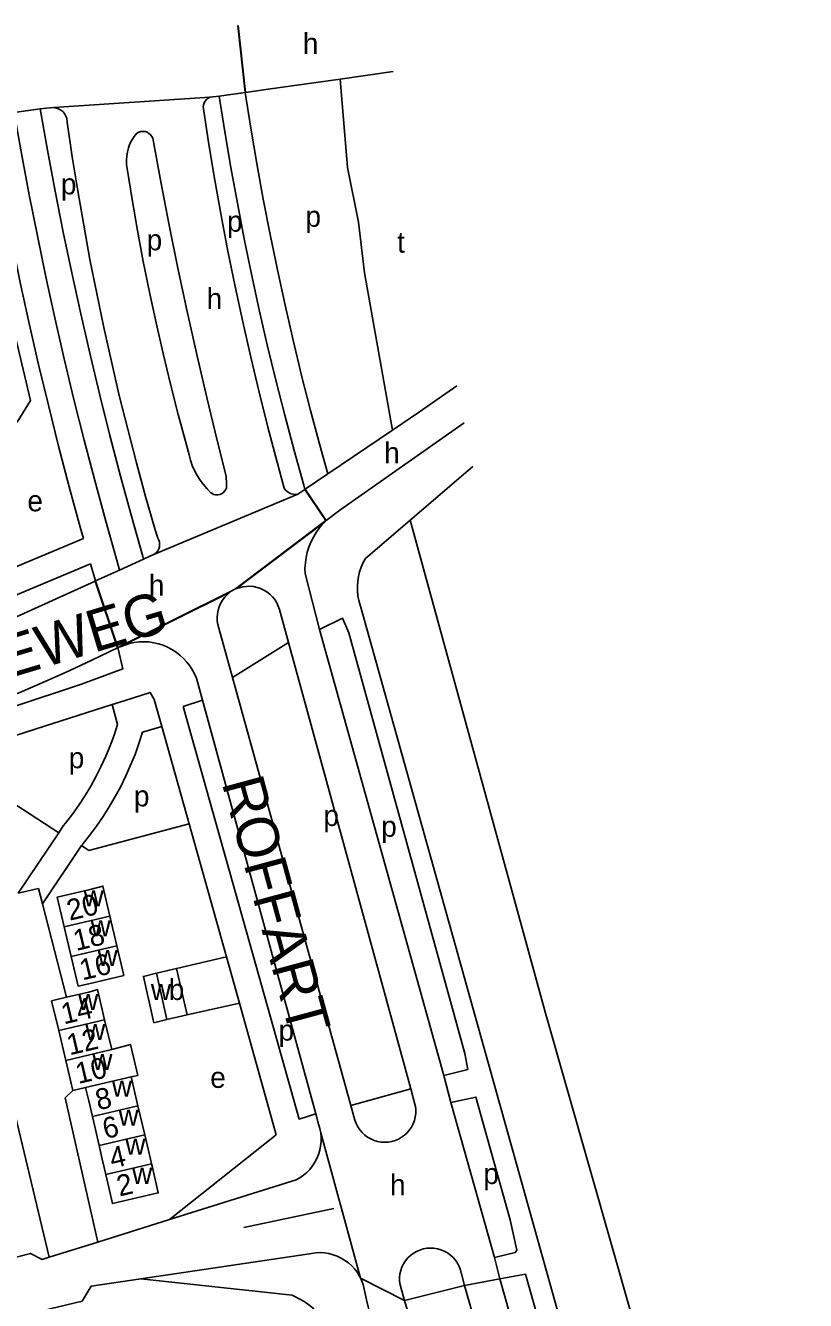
# Model space of a CAD drawing. Extents: x 157646 to 159241, y 379213 to 381217.
# Drawn here: x 158987.9 to 159137, y 380973 to 381216.8 of the extents above; entities that cross this region are included whole.
import ezdxf

# ---------------------------------------------------------------- set-up
doc = ezdxf.new("R2010")
doc.units = 0
for name, color, linetype in [('BLT_Basislijn', 7, 'Continuous'), ('BLT_Bebouwing', 7, 'Continuous'), ('BLT_Centroide', 7, 'Continuous'), ('BLT_Huisnummer', 7, 'Continuous'), ('BLT_Huisnummer_ tussenligend', 7, 'Continuous'), ('BLT_Onderverdeling_panden', 7, 'Continuous'), ('BLT_Straatnaam_hoofdweg', 7, 'Continuous'), ('BLT_Vlakafsluiter', 7, 'Continuous')]:
    doc.layers.add(name, color=color, linetype=linetype)

msp = doc.modelspace()

# ---------------------------------------------------------------- linework, layer by layer
at = {"layer": 'BLT_Basislijn'}
for p, q in [((159058.2, 381207.99), (159048.02, 381206.55)), ((159034.27, 381204.61), (159048.02, 381206.55)), ((159023.15, 381203.13), (159024.93, 381203.32)), ((159024.93, 381203.32), (159029.88, 381204)), ((159029.88, 381204), (159029.93, 381204.01)), ((159029.93, 381204.01), (159034.27, 381204.61)), ((158985.74, 381200.19), (158990.7, 381200.86)), ((158990.7, 381200.86), (158991.92, 381201.02)), ((158991.92, 381201.02), (158993.29, 381201.11)), ((158995.77, 381199.08), (158995.87, 381198.3)), ((159045.68, 381131.05), (159058.05, 381139.43)), ((159073.44, 381132.44), (159061.42, 381122.18)), ((159026.24, 381130.64), (159026.31, 381129.18)), ((159041.36, 381128.13), (159045.68, 381131.05)), ((159039.96, 381127.17), (159041.32, 381128.1)), ((159041.32, 381128.1), (159041.36, 381128.13)), ((159047.97, 381124.14), (159045.36, 381122.16)), ((159045.1, 381121.9), (159045.32, 381122.13)), ((159045.36, 381122.16), (159045.32, 381122.13)), ((159061.42, 381122.18), (159052.88, 381114.89)), ((158998.95, 381118.71), (158958.63, 381101.7)), ((159010.47, 381114.75), (159011.68, 381115.3)), ((159012.58, 381115.68), (159011.68, 381115.3)), ((159000.32, 381113.86), (158956.44, 381095.51)), ((159000.32, 381113.86), (159001.27, 381110.58)), ((159001.27, 381110.58), (159005.87, 381112.66)), ((159005.87, 381112.66), (159010.47, 381114.75)), ((159041.33, 381112), (159044.1, 381101.28)), ((159026.86, 381108.37), (159026.96, 381108.48)), ((159026.96, 381108.48), (159028.07, 381109.07)), ((159028.07, 381109.07), (159028.22, 381109.11)), ((159038.16, 381098.82), (159036.43, 381105.12)), ((159024.84, 381101.57), (159027.45, 381092.14)), ((159044.1, 381101.28), (159067.87, 381016.03)), ((159005.55, 381097.83), (159005.98, 381097.99)), ((159038.16, 381098.82), (159027.45, 381092.14)), ((159061.54, 381013.44), (159038.16, 381098.82)), ((159005.5, 381097.81), (159005.55, 381097.83)), ((159020.57, 381091.97), (159021.7, 381087.81)), ((159027.45, 381092.14), (159050.11, 381010.24)), ((159005.5, 381083.11), (159004.49, 381086.94)), ((159012.49, 381087.89), (159013.94, 381082.74)), ((159018.05, 381086.59), (159021.7, 381087.81)), ((159018.05, 381086.59), (159040.2, 381007.62)), ((159021.7, 381087.81), (159043.38, 381008.65)), ((159010.28, 381081.64), (159013.94, 381082.74)), ((159013.94, 381082.74), (159019.15, 381064.15)), ((159000, 381059.01), (159019.15, 381064.15)), ((159019.15, 381064.15), (159026.3, 381038.67)), ((158994.25, 381062.43), (158986.48, 381050.9)), ((158995.12, 381063.72), (158994.25, 381062.43)), ((158998.63, 381060.01), (158991.13, 381048.86)), ((159000, 381059.01), (158998.63, 381060.01)), ((158986.48, 381050.9), (158990.38, 381051.79)), ((158990.38, 381051.79), (158991.13, 381048.86)), ((158991.13, 381048.86), (158995.73, 381030.98)), ((159016.73, 381036.46), (159026.3, 381038.67)), ((159026.3, 381038.67), (159028.78, 381029.82)), ((159018.8, 381027.59), (159028.78, 381029.82)), ((159028.78, 381029.82), (159035.84, 381004.65)), ((159067.87, 381016.03), (159069.18, 381010.85)), ((159061.54, 381013.44), (159050.11, 381010.24)), ((159062.4, 381010.28), (159061.54, 381013.44)), ((159050.11, 381010.24), (159050.88, 381007.46)), ((159077.52, 380981.2), (159069.18, 381010.85)), ((158992.44, 380981.26), (158985.59, 381009.81)), ((159040.2, 381007.62), (159043.38, 381008.65)), ((159043.38, 381008.65), (159043.91, 381006.69)), ((159035.84, 381004.65), (159015.44, 380988.46)), ((159015.44, 380988.46), (159039.61, 380996.03)), ((159001.7, 380984.15), (159015.44, 380988.46)), ((159046.86, 380990.59), (159029.63, 380986.96)), ((158992.44, 380981.26), (159001.7, 380984.15)), ((159041.76, 380981.8), (159009.95, 380977.12)), ((159077.52, 380981.2), (159078.6, 380977.14)), ((159038.87, 380973.99), (159009.95, 380977.12)), ((159060.36, 380973), (159059.49, 380975.98)), ((159071.23, 380978.04), (159071.84, 380975.87)), ((159060.36, 380973), (159071.84, 380975.87)), ((159062.85, 380964.45), (159060.36, 380973))]:
    msp.add_line(p, q, dxfattribs=at)
for points in [[(159048.02, 381206.55), (159049.45, 381189.62), (159051.55, 381179.21), (159052.73, 381169.5), (159058.05, 381139.43)], [(159023.15, 381203.13), (159022.8, 381202.89), (159022.48, 381202.66), (159022.22, 381202.36), (159022.03, 381202.01), (159021.91, 381201.64), (159021.87, 381201.25), (159021.9, 381200.87)], [(159024.93, 381203.32), (159026.01, 381196.47), (159027.16, 381189.64), (159028.4, 381182.82), (159029.71, 381176.02), (159031.11, 381169.23), (159032.58, 381162.46), (159034.12, 381155.71), (159035.75, 381148.97), (159037.46, 381142.26), (159039.24, 381135.56), (159041.1, 381128.88), (159041.32, 381128.1)], [(159029.88, 381204), (159030.96, 381197.19), (159032.11, 381190.39), (159033.34, 381183.6), (159034.65, 381176.82), (159036.04, 381170.06), (159037.51, 381163.32), (159039.05, 381156.6), (159040.68, 381149.89), (159042.38, 381143.2), (159044.15, 381136.53), (159045.68, 381131.05)], [(158990.7, 381200.86), (158992.09, 381192.99), (158993.56, 381185.14), (158995.11, 381177.3), (158996.74, 381169.48), (158998.45, 381161.68), (159000.24, 381153.89), (159002.1, 381146.12), (159004.04, 381138.38), (159006.06, 381130.65), (159008.15, 381122.94), (159010.33, 381115.25), (159010.47, 381114.75)], [(158993.29, 381201.11), (158993.76, 381201.03), (158994.21, 381200.87), (158994.63, 381200.64), (158995, 381200.34), (158995.32, 381199.98), (158995.57, 381199.57), (158995.77, 381199.08)], [(159021.9, 381200.87), (159022.96, 381194.04), (159024.09, 381187.23), (159025.31, 381180.44), (159026.6, 381173.65), (159027.97, 381166.89), (159029.42, 381160.14), (159030.94, 381153.4), (159032.55, 381146.69), (159034.23, 381139.99), (159035.99, 381133.31), (159037.36, 381128.33)], [(158980.78, 381199.53), (158982.23, 381191.34), (158983.71, 381183.44), (158985.27, 381175.55), (158986.9, 381167.68), (158988.62, 381159.83), (158990.41, 381151.99), (158992.28, 381144.18), (158994.23, 381136.38), (158996.25, 381128.6), (158998.36, 381120.84), (158998.95, 381118.71)], [(158985.74, 381200.19), (158987.13, 381192.3), (158988.61, 381184.43), (158990.16, 381176.57), (158991.79, 381168.72), (158993.5, 381160.89), (158995.29, 381153.08), (158997.16, 381145.29), (158999.1, 381137.51), (159001.12, 381129.76), (159003.22, 381122.02), (159005.39, 381114.31), (159005.87, 381112.66)], [(158995.87, 381198.3), (158996.84, 381191.72), (158997.89, 381185.16), (158999.02, 381178.6), (159000.22, 381172.06), (159001.51, 381165.54), (159002.87, 381159.03), (159004.31, 381152.53), (159005.83, 381146.06), (159007.43, 381139.6), (159009.11, 381133.17), (159010.86, 381126.75), (159012.69, 381120.36)], [(159007.32, 381189.45), (159007.21, 381190.25), (159007.18, 381191.05), (159007.24, 381191.85), (159007.37, 381192.64), (159007.58, 381193.41), (159007.87, 381194.16), (159008.22, 381194.88), (159008.65, 381195.56), (159009.19, 381196.24)], [(159009.19, 381196.24), (159009.56, 381196.43), (159009.95, 381196.53), (159010.36, 381196.56), (159010.76, 381196.51), (159011.14, 381196.38), (159011.49, 381196.18), (159011.8, 381195.91), (159012.05, 381195.59), (159012.23, 381195.23)], [(159012.23, 381195.23), (159013.75, 381186.93), (159015.35, 381178.65), (159017.02, 381170.38), (159018.78, 381162.12), (159020.62, 381153.89), (159022.53, 381145.67), (159024.52, 381137.47), (159026.24, 381130.64)], [(159007.32, 381189.45), (159008.27, 381183.52), (159009.29, 381177.6), (159010.4, 381171.69), (159011.59, 381165.8), (159012.85, 381159.92), (159014.19, 381154.06), (159015.61, 381148.22), (159017.11, 381142.4), (159018.68, 381136.6), (159019.02, 381135.41)], [(159058.05, 381139.43), (159063.21, 381142.92), (159070.32, 381147.9)], [(159047.97, 381124.14), (159071.75, 381140.84)], [(159023.35, 381127.46), (159022.6, 381128.21), (159021.9, 381129.01), (159021.27, 381129.86), (159020.71, 381130.75), (159020.21, 381131.69), (159019.78, 381132.66), (159019.43, 381133.66), (159019.16, 381134.68), (159019.02, 381135.41)], [(159026.31, 381129.18), (159026.34, 381128.8), (159026.29, 381128.42), (159026.16, 381128.06), (159025.96, 381127.74), (159025.7, 381127.46), (159025.38, 381127.25), (159025.03, 381127.1), (159024.65, 381127.04), (159024.27, 381127.05), (159023.9, 381127.14), (159023.56, 381127.3), (159023.35, 381127.46)], [(159037.36, 381128.33), (159037.62, 381127.97), (159037.93, 381127.66), (159038.3, 381127.42), (159038.71, 381127.24), (159039.14, 381127.15), (159039.58, 381127.13), (159039.96, 381127.17)], [(159012.69, 381120.36), (159013.16, 381118.76)], [(159041.33, 381112), (159041.32, 381113.03), (159041.39, 381114.06), (159041.55, 381115.08), (159041.77, 381116.08), (159042.08, 381117.07), (159042.46, 381118.03), (159042.92, 381118.95), (159043.45, 381119.84), (159044.04, 381120.68), (159044.7, 381121.48), (159045.1, 381121.9)], [(159061.42, 381122.18), (159087.3, 381027.91), (159116.68, 380924.86), (159137, 380849.84)], [(159013.16, 381118.76), (159013.36, 381118.38), (159013.48, 381117.98), (159013.53, 381117.55), (159013.49, 381117.13), (159013.38, 381116.72), (159013.2, 381116.34), (159012.94, 381116), (159012.58, 381115.68)], [(159052.88, 381114.89), (159052.44, 381114.08), (159052.06, 381113.23), (159051.77, 381112.35), (159051.54, 381111.45), (159051.4, 381110.54), (159051.33, 381109.61), (159051.35, 381108.68), (159051.45, 381107.76), (159051.62, 381106.85), (159051.87, 381105.96), (159051.94, 381105.75)], [(158939.33, 381086.39), (158971.92, 381097.26), (159001.22, 381110.56)], [(159001.22, 381110.56), (159001.27, 381110.58)], [(159024.84, 381101.57), (159024.66, 381102.24), (159024.55, 381102.92), (159024.52, 381103.62), (159024.58, 381104.31), (159024.71, 381105), (159024.92, 381105.66), (159025.2, 381106.3), (159025.56, 381106.9), (159025.98, 381107.45), (159026.46, 381107.95), (159026.86, 381108.37)], [(159028.22, 381109.11), (159028.74, 381109.29), (159029.42, 381109.46), (159030.11, 381109.55), (159030.81, 381109.57), (159031.5, 381109.5), (159032.18, 381109.36), (159032.84, 381109.14), (159033.47, 381108.84), (159034.06, 381108.48), (159034.61, 381108.05), (159035.1, 381107.55), (159035.54, 381107.01), (159035.91, 381106.42), (159036.21, 381105.79), (159036.43, 381105.12)], [(159051.94, 381105.75), (159100, 380933.91), (159125.11, 380844.8)], [(159044.1, 381101.28), (159048.5, 381103.46), (159049.69, 381100.66), (159071.87, 381020.19), (159072.43, 381017.15), (159067.87, 381016.03)], [(159005.98, 381097.99), (159007.76, 381098.65), (159008.68, 381098.83), (159009.61, 381098.93), (159010.54, 381098.96), (159011.47, 381098.91), (159012.4, 381098.77), (159013.31, 381098.56), (159014.2, 381098.27), (159015.06, 381097.9), (159015.89, 381097.47), (159016.67, 381096.96), (159017.41, 381096.39), (159018.1, 381095.76), (159018.73, 381095.07), (159019.3, 381094.33), (159019.81, 381093.54), (159020.24, 381092.71), (159020.57, 381091.97)], [(158968.82, 381082.45), (158971.83, 381081.99), (158998.58, 381090.83), (159006.51, 381093.78), (159005.55, 381097.83)], [(159005.5, 381097.81), (159000.72, 381095.48), (158996.26, 381093.4), (158991.76, 381091.39), (158987.23, 381089.46), (158982.67, 381087.6), (158978.08, 381085.81), (158973.46, 381084.1), (158968.82, 381082.45)], [(159004.49, 381086.94), (159006.74, 381087.66), (159011.73, 381089.24), (159012.49, 381087.89)], [(158983.41, 381080.21), (158989.74, 381082.21), (159004.49, 381086.94)], [(159005.5, 381083.11), (159004.83, 381081.07), (159004.09, 381079.07), (159003.27, 381077.09), (159002.38, 381075.14), (159001.42, 381073.23), (159000.38, 381071.35), (158999.28, 381069.52), (158998.11, 381067.72), (158996.87, 381065.98), (158995.57, 381064.28), (158995.12, 381063.72)], [(159010.28, 381081.64), (159009.59, 381079.51), (159008.83, 381077.41), (159007.99, 381075.35), (159007.07, 381073.31), (159006.09, 381071.3), (159005.03, 381069.34), (159003.9, 381067.41), (159002.71, 381065.52), (159001.45, 381063.68), (159000.12, 381061.88), (158998.73, 381060.14), (158998.63, 381060.01)], [(158983.41, 381080.21), (158986.05, 381067.78), (158994.25, 381062.43)], [(158996.96, 381013.16), (158995.48, 381011.73), (159001.7, 380984.15)], [(159050.88, 381007.46), (159051.11, 381006.81), (159051.42, 381006.2), (159051.8, 381005.62), (159052.24, 381005.09), (159052.74, 381004.62), (159053.29, 381004.2), (159053.88, 381003.86), (159054.52, 381003.58), (159055.18, 381003.38), (159055.85, 381003.26), (159056.54, 381003.22), (159057.23, 381003.25), (159057.91, 381003.37), (159058.57, 381003.57), (159059.2, 381003.83), (159059.8, 381004.18), (159060.36, 381004.58), (159060.86, 381005.05), (159061.31, 381005.58), (159061.69, 381006.15), (159062, 381006.77), (159062.24, 381007.41), (159062.41, 381008.08), (159062.49, 381008.76), (159062.5, 381009.45), (159062.43, 381010.14), (159062.4, 381010.28)], [(159077.52, 380981.2), (159081.51, 380982.14), (159081.83, 380982.62), (159080.56, 380988.37), (159073.96, 381011.86), (159069.18, 381010.85)], [(159044.32, 381005.02), (159044.17, 381005.84), (159043.91, 381006.69)], [(159039.61, 380996.03), (159040.33, 380996.44), (159041.02, 380996.91), (159041.65, 380997.45), (159042.23, 380998.05), (159042.76, 380998.7), (159043.21, 380999.4), (159043.6, 381000.14), (159043.91, 381000.91), (159044.15, 381001.71), (159044.31, 381002.53), (159044.4, 381003.36), (159044.4, 381004.19), (159044.32, 381005.02)], [(158967.75, 380976.53), (158988.83, 380981.97), (158991.1, 380980.83), (158992.44, 380981.26)], [(159041.76, 380981.8), (159042.58, 380981.98), (159043.4, 380982.09), (159044.24, 380982.12), (159045.07, 380982.07), (159045.9, 380981.93), (159046.71, 380981.73), (159047.49, 380981.44), (159048.25, 380981.08), (159048.96, 380980.65), (159049.64, 380980.15), (159050.26, 380979.6), (159050.83, 380978.98), (159051.33, 380978.31), (159051.77, 380977.6), (159051.95, 380977.23)], [(159059.49, 380975.98), (159059.4, 380976.67), (159059.4, 380977.36), (159059.48, 380978.04), (159059.63, 380978.72), (159059.86, 380979.36), (159060.17, 380979.98), (159060.54, 380980.56), (159060.98, 380981.1), (159061.48, 380981.57), (159062.03, 380981.99), (159062.62, 380982.34), (159063.26, 380982.62), (159063.92, 380982.83), (159064.59, 380982.95), (159065.28, 380983), (159065.97, 380982.97), (159066.65, 380982.86), (159067.32, 380982.67), (159067.95, 380982.4), (159068.56, 380982.07), (159069.12, 380981.66), (159069.62, 380981.2), (159070.08, 380980.67), (159070.46, 380980.1), (159070.78, 380979.49), (159071.03, 380978.85), (159071.2, 380978.18), (159071.23, 380978.04)], [(159009.95, 380977.12), (159000.45, 380975.73), (158998.72, 380972.84), (158953.4, 380962)], [(159051.95, 380977.23), (159052.14, 380976.85), (159052.45, 380976.01)], [(159052.45, 380976.01), (159053.07, 380973.13), (159053.58, 380971.02)], [(159126.48, 380806.41), (159129.85, 380807.86), (159130.83, 380808.7), (159130.78, 380809.42), (159115.53, 380863.06), (159100, 380919.55), (159083.47, 380977.99), (159078.6, 380977.14)], [(159078.6, 380977.14), (159100, 380901.47), (159124.92, 380811.25), (159126.48, 380806.41)], [(159045.13, 380968.99), (159044.45, 380969.86), (159043.72, 380970.67), (159042.92, 380971.42), (159042.08, 380972.12), (159041.18, 380972.75), (159040.24, 380973.32), (159039.27, 380973.82), (159038.87, 380973.99)], [(159071.84, 380975.87), (159087.11, 380922.26), (159085.67, 380921.97), (159071.52, 380944.8)]]:
    msp.add_lwpolyline(points, dxfattribs=at)
at = {"layer": 'BLT_Bebouwing'}
for p, q in [((158996.64, 381038.74), (158995.29, 381044.42)), ((159004.03, 381046.5), (159005.36, 381040.81)), ((158997.99, 381033.06), (158996.64, 381038.74)), ((159016.73, 381036.46), (159018.8, 381027.59)), ((158992.89, 381030.3), (158995.73, 381030.98)), ((158994.24, 381024.59), (158992.89, 381030.3)), ((158995.73, 381030.98), (158998.26, 381031.58)), ((159003.02, 381026.67), (159004.37, 381020.96)), ((158995.6, 381018.87), (158994.24, 381024.59)), ((158996.96, 381013.16), (158995.6, 381018.87)), ((159008.07, 381015.74), (159009.38, 381010.19)), ((158999.39, 381013.73), (158996.96, 381013.16)), ((159009.38, 381010.19), (159010.69, 381004.63)), ((159001.95, 381002.62), (159000.68, 381008.18)), ((159010.69, 381004.63), (159011.77, 381000.01)), ((159002.55, 381000), (159001.95, 381002.62)), ((159003.24, 380997.06), (159002.55, 381000)), ((159011.99, 380999.08), (159011.77, 381000.01))]:
    msp.add_line(p, q, dxfattribs=at)
for points in [[(158958.61, 381134.8), (158955.21, 381134), (158954.48, 381132.8), (158956.07, 381125.51), (158956.37, 381124.2), (158957.53, 381119.25), (158961.72, 381116.65), (158977.21, 381120.29), (158979.83, 381124.52), (158977.24, 381135.57), (158979.6, 381139.39), (158986.27, 381140.95), (158988.84, 381145.09), (158984.16, 381165.02), (158979.93, 381167.64), (158977.58, 381167.09), (158973.79, 381169.43), (158969.14, 381189.23), (158964.95, 381191.82), (158949.39, 381188.17), (158947.01, 381183.97)], [(158995.29, 381044.42), (158993.94, 381050.1), (159000.01, 381051.5), (159002.69, 381052.24), (159004.03, 381046.5)], [(159005.36, 381040.81), (159006.68, 381035.14), (159000, 381033.54), (158997.99, 381033.06)], [(159014.93, 381026.68), (159012.43, 381026.1), (159010.42, 381034.96), (159012.93, 381035.55)], [(159012.93, 381035.55), (159016.73, 381036.46)], [(158998.26, 381031.58), (159000.01, 381031.96), (159001.65, 381032.42), (159003.02, 381026.67)], [(159018.8, 381027.59), (159014.93, 381026.68)], [(159004.37, 381020.96), (159007.96, 381021.96), (159009.34, 381016.03), (159008.07, 381015.74)], [(159000.68, 381008.18), (159000, 381011.17), (158999.39, 381013.73)], [(159011.99, 380999.08), (159012.14, 380998.43), (159013.27, 380993.56), (159004.52, 380991.5), (159003.24, 380997.06)]]:
    msp.add_lwpolyline(points, dxfattribs=at)
at = {"layer": 'BLT_Onderverdeling_panden'}
for p, q in [((158995.29, 381044.42), (159004.03, 381046.5)), ((158996.64, 381038.74), (159005.36, 381040.81)), ((159014.93, 381026.68), (159012.93, 381035.55)), ((158994.24, 381024.59), (159003.02, 381026.67)), ((158995.6, 381018.87), (159004.37, 381020.96)), ((158999.39, 381013.73), (159008.07, 381015.74)), ((159000.68, 381008.18), (159009.38, 381010.19)), ((159001.95, 381002.62), (159010.69, 381004.63)), ((159003.24, 380997.06), (159011.99, 380999.08))]:
    msp.add_line(p, q, dxfattribs=at)
at = {"layer": 'BLT_Vlakafsluiter'}
for p, q in [((159029.88, 381204), (159028.51, 381216.8)), ((159029.93, 381204.01), (159028.56, 381216.81)), ((158993.29, 381201.11), (159023.15, 381203.13)), ((159012.58, 381115.68), (159039.96, 381127.17)), ((159045.32, 381122.13), (159041.32, 381128.1)), ((159045.36, 381122.16), (159041.36, 381128.13)), ((159028.07, 381109.07), (159045.32, 381122.13)), ((159028.22, 381109.11), (159045.1, 381121.9)), ((159005.5, 381097.81), (159001.22, 381110.56)), ((159005.55, 381097.83), (159001.27, 381110.58)), ((159026.96, 381108.48), (159005.55, 381097.83)), ((159026.86, 381108.37), (159005.98, 381097.99)), ((159044.32, 381005.02), (159051.95, 380977.23)), ((159060.36, 380973), (159051.95, 380977.23)), ((159071.84, 380975.87), (159078.6, 380977.14))]:
    msp.add_line(p, q, dxfattribs=at)

# ---------------------------------------------------------------- texts
at = {"layer": 'BLT_Centroide'}
for s, p in [('h', (159040.91, 381211.37)), ('p', (158994.66, 381184.51)), ('p', (159041.41, 381178.31)), ('p', (159026.42, 381177.37)), ('p', (159011.06, 381173.81)), ('t', (159058.93, 381173.35)), ('h', (159022.52, 381162.56)), ('h', (159056.46, 381133.09)), ('e', (158988.25, 381123.9)), ('h', (159011.47, 381107.76)), ('p', (158996.16, 381074.76)), ('p', (159008.62, 381067.46)), ('p', (159044.85, 381063.71)), ('p', (159055.9, 381061.64)), ('w', (158998.98, 381048.34)), ('w', (159000.33, 381042.62)), ('w', (159001.66, 381036.94)), ('b', (159015.28, 381030.44)), ('w', (159011.86, 381030.44)), ('w', (158997.95, 381028.5)), ('w', (158999.3, 381022.78)), ('p', (159036.28, 381022.67)), ('w', (159000.66, 381017.06)), ('w', (159004.39, 381011.97)), ('e', (159023.21, 381013.63)), ('w', (159005.67, 381006.41)), ('w', (159006.97, 381000.84)), ('w', (159008.26, 380995.28)), ('p', (159075.42, 380995.23)), ('h', (159057.58, 380993.1))]:
    msp.add_text(s, height=4, dxfattribs=at).set_placement(p)
at = {"layer": 'BLT_Huisnummer'}
for s, rotation, p in [('20', 13.3757, (158996.32, 381045.58)), ('16', 13.4594, (158998.77, 381034.17)), ('14', 13.2212, (158995.22, 381025.76)), ('10', 13.2212, (158997.97, 381014.36)), ('6', 13.2212, (159003.15, 381003.83)), ('2', 13.2212, (159005.85, 380992.84))]:
    msp.add_text(s, height=4, rotation=rotation, dxfattribs=at).set_placement(p)
at = {"layer": 'BLT_Huisnummer_ tussenligend'}
for s, rotation, p in [('18', 13.4594, (158997.56, 381039.8)), ('12', 13.2212, (158996.31, 381019.84)), ('8', 13.2212, (159001.79, 381009.31)), ('4', 13.2212, (159004.47, 380998.17))]:
    msp.add_text(s, height=4, rotation=rotation, dxfattribs=at).set_placement(p)
at = {"layer": 'BLT_Straatnaam_hoofdweg'}
for s, rotation, p in [('MEERVELDHOVENSEWEG', 16.7281, (158884.82, 381061.92)), ('ROFFART', 285.155, (159025.37, 381072.01))]:
    msp.add_text(s, height=8, rotation=rotation, dxfattribs=at).set_placement(p)

doc.saveas('drawing.dxf')
